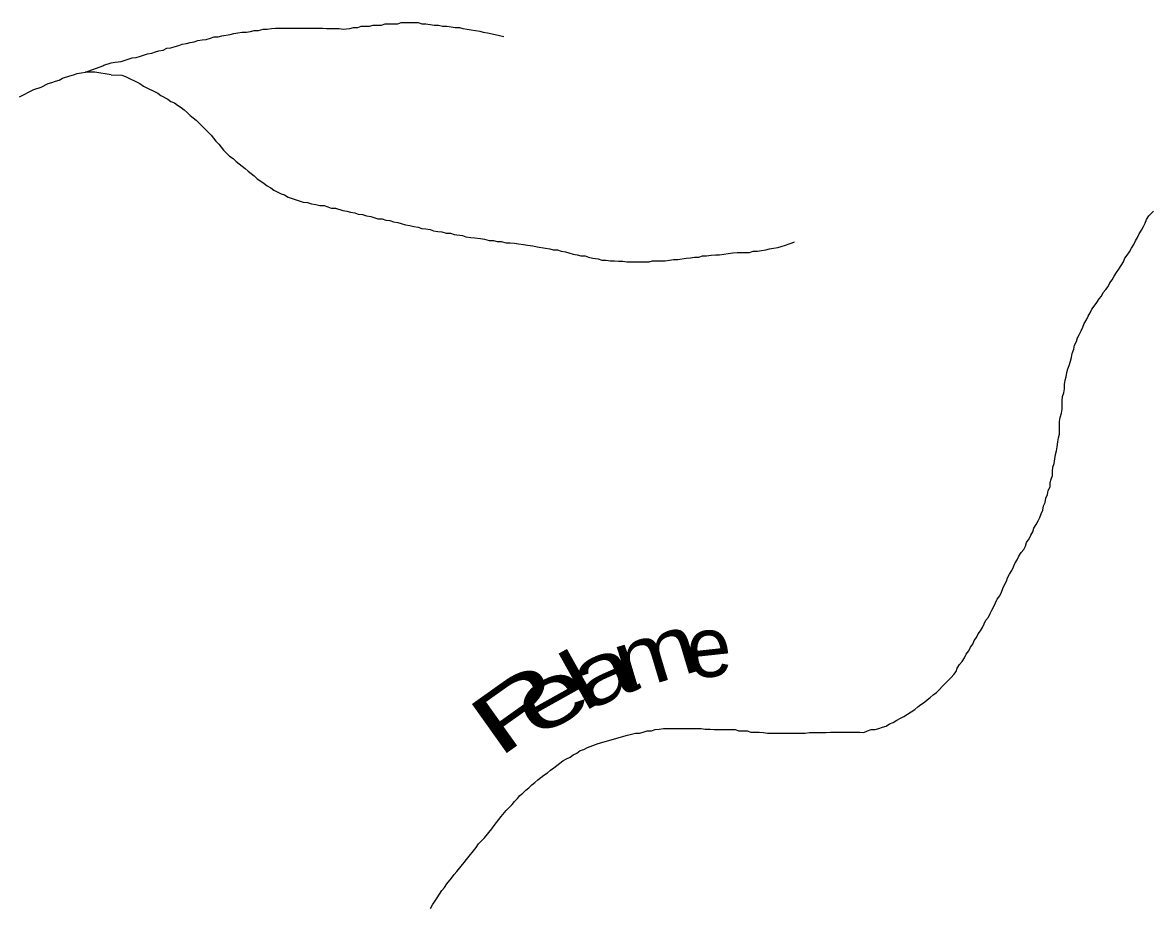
# Model space of a CAD drawing. Extents: x 652.3 to 678, y 7316.9 to 7344.9.
# Drawn here: x 662.771 to 664.275, y 7321.355 to 7322.532 of the extents above; entities that cross this region are included whole.
import ezdxf
from ezdxf.enums import TextEntityAlignment as Align

# ---------------------------------------------------------------- set-up
doc = ezdxf.new("R2010")
doc.units = 0
doc.header["$LTSCALE"] = 0.032
doc.layers.add('61', color=7, linetype='Continuous')
doc.layers.add('7', color=7, linetype='Continuous', lineweight=25)

msp = doc.modelspace()

# ---------------------------------------------------------------- linework, layer by layer
at = {"layer": '7'}
for points in [[(662.878, 7322.4749), (662.8796, 7322.4757), (662.8891, 7322.4789), (662.8947, 7322.4797), (662.9027, 7322.4805), (662.917, 7322.4852), (662.9225, 7322.486), (662.9281, 7322.4876), (662.9377, 7322.4908), (662.9432, 7322.4916), (662.948, 7322.4932), (662.9528, 7322.4948), (662.9584, 7322.4956), (662.9631, 7322.498), (662.9687, 7322.4988), (662.9743, 7322.5003), (662.979, 7322.5019), (662.9838, 7322.5035), (662.9894, 7322.5043), (662.9942, 7322.5059), (662.9997, 7322.5067), (663.0045, 7322.5083), (663.0101, 7322.5091), (663.0156, 7322.5099), (663.0212, 7322.5115), (663.026, 7322.5131), (663.0316, 7322.5131), (663.0363, 7322.5147), (663.0475, 7322.5163), (663.0522, 7322.5179), (663.0578, 7322.5186), (663.0634, 7322.5194), (663.069, 7322.5194), (663.0745, 7322.5202), (663.0793, 7322.5218), (663.0849, 7322.5218), (663.0912, 7322.5234), (663.0968, 7322.5234), (663.1024, 7322.5242), (663.1079, 7322.525), (663.17, 7322.525), (663.1756, 7322.5242), (663.1923, 7322.5242), (663.1979, 7322.5234), (663.2066, 7322.5242), (663.2114, 7322.5258), (663.217, 7322.5258), (663.2217, 7322.5274), (663.2329, 7322.5274), (663.2376, 7322.529), (663.2488, 7322.529), (663.2536, 7322.5306), (663.2703, 7322.5306), (663.275, 7322.5322), (663.2973, 7322.5322), (663.3021, 7322.5306), (663.3077, 7322.5306), (663.3132, 7322.5298), (663.3188, 7322.529), (663.3244, 7322.529), (663.3299, 7322.5274), (663.3355, 7322.5274), (663.3411, 7322.5266), (663.3467, 7322.5258), (663.3522, 7322.5258), (663.357, 7322.5242), (663.3626, 7322.5234), (663.3681, 7322.5226), (663.3793, 7322.521), (663.384, 7322.5194), (663.3896, 7322.5186), (663.4, 7322.5163), (663.4112, 7322.5137)], [(662.8549, 7322.4661), (662.8549, 7322.4661), (662.878, 7322.4749)], [(662.7674, 7322.4335), (662.7865, 7322.4431), (662.796, 7322.4462), (662.8056, 7322.451), (662.8104, 7322.4526), (662.8151, 7322.4542), (662.8199, 7322.4558), (662.8247, 7322.4582), (662.8342, 7322.4614), (662.839, 7322.4629), (662.8438, 7322.4645), (662.8493, 7322.4653), (662.8549, 7322.4661)], [(662.8891, 7322.4629), (662.8676, 7322.4661), (662.8549, 7322.4661)], [(662.8891, 7322.4629), (662.9035, 7322.4622), (662.9082, 7322.4606), (662.9273, 7322.451), (662.9321, 7322.4478), (662.9512, 7322.4383), (662.9552, 7322.4351), (662.9647, 7322.4303), (662.9687, 7322.4271), (662.9735, 7322.4256), (662.9775, 7322.4224), (662.9822, 7322.4192), (662.9862, 7322.416), (662.9902, 7322.4128), (662.9942, 7322.4088), (662.9981, 7322.4057), (663.0021, 7322.4025), (663.018, 7322.3866), (663.022, 7322.3826), (663.0284, 7322.3746), (663.0324, 7322.3706), (663.0387, 7322.3627), (663.0467, 7322.3547), (663.0514, 7322.3516), (663.0554, 7322.3476), (663.0594, 7322.3444), (663.0634, 7322.3412), (663.0674, 7322.338), (663.0713, 7322.3348), (663.0753, 7322.3317), (663.0793, 7322.3285), (663.0833, 7322.3245), (663.0881, 7322.3213), (663.0928, 7322.3181), (663.0968, 7322.315), (663.1016, 7322.3126), (663.1056, 7322.3094), (663.1151, 7322.3046), (663.1199, 7322.303), (663.1247, 7322.2998), (663.139, 7322.2951), (663.1445, 7322.2935), (663.1501, 7322.2927), (663.1557, 7322.2911), (663.1613, 7322.2903), (663.1668, 7322.2887), (663.1724, 7322.2887), (663.1772, 7322.2871), (663.1819, 7322.2855), (663.1875, 7322.2855), (663.1971, 7322.2823), (663.2026, 7322.2815), (663.2074, 7322.2799), (663.213, 7322.2791), (663.2177, 7322.2776), (663.2233, 7322.2768), (663.2289, 7322.2752), (663.2345, 7322.2744), (663.244, 7322.2712), (663.2496, 7322.2712), (663.2544, 7322.2696), (663.2599, 7322.2688), (663.2647, 7322.2672), (663.2703, 7322.2664), (663.275, 7322.2648), (663.2806, 7322.2632), (663.2862, 7322.2624), (663.2917, 7322.2608), (663.2973, 7322.26), (663.3021, 7322.2585), (663.3077, 7322.2577), (663.3132, 7322.2569), (663.318, 7322.2553), (663.3236, 7322.2545), (663.3291, 7322.2537), (663.3347, 7322.2521), (663.3403, 7322.2521), (663.3451, 7322.2505), (663.3562, 7322.2489), (663.361, 7322.2473), (663.3673, 7322.2465), (663.3729, 7322.2457), (663.3801, 7322.2449), (663.3856, 7322.2441), (663.392, 7322.2425), (663.3976, 7322.2425), (663.4023, 7322.241), (663.4079, 7322.241), (663.4143, 7322.2394), (663.4199, 7322.2394), (663.4254, 7322.2386), (663.431, 7322.2378), (663.4374, 7322.237), (663.4429, 7322.2362), (663.4501, 7322.2354), (663.4557, 7322.2338), (663.4668, 7322.2322), (663.4724, 7322.2314), (663.4771, 7322.2298), (663.4827, 7322.2298), (663.4875, 7322.2282)], [(664.1161, 7321.8598), (664.1193, 7321.8646), (664.1217, 7321.8694), (664.124, 7321.8741), (664.1256, 7321.8789), (664.128, 7321.8837), (664.1288, 7321.8893), (664.1312, 7321.894), (664.132, 7321.8996), (664.1344, 7321.9044), (664.1352, 7321.9099), (664.1376, 7321.9147), (664.1376, 7321.9203), (664.1392, 7321.9251), (664.1407, 7321.9298), (664.1407, 7321.9354), (664.1415, 7321.941), (664.1431, 7321.9458), (664.1439, 7321.9521), (664.1447, 7321.9577), (664.1463, 7321.9625), (664.1471, 7321.968), (664.1479, 7321.9744), (664.1487, 7321.98), (664.1503, 7321.9847), (664.1503, 7321.9903), (664.1503, 7321.9959), (664.1503, 7322.0014), (664.1511, 7322.007), (664.1527, 7322.0126), (664.1535, 7322.0182), (664.1535, 7322.0237), (664.1535, 7322.0293), (664.1543, 7322.0349), (664.1559, 7322.0396), (664.1567, 7322.0452), (664.1567, 7322.0508), (664.1575, 7322.0564), (664.159, 7322.0611), (664.1598, 7322.0667), (664.1614, 7322.0715), (664.163, 7322.0762), (664.1646, 7322.0818), (664.1662, 7322.0866), (664.167, 7322.0922), (664.1694, 7322.0977), (664.1702, 7322.1033), (664.1726, 7322.1081), (664.1742, 7322.1128), (664.1766, 7322.1176), (664.1789, 7322.1224), (664.1813, 7322.1272), (664.1829, 7322.1319), (664.1861, 7322.1367), (664.1885, 7322.1415), (664.1909, 7322.1463), (664.1933, 7322.151), (664.1964, 7322.155), (664.1996, 7322.1598), (664.2028, 7322.1646), (664.206, 7322.1685), (664.2084, 7322.1733), (664.2116, 7322.1773), (664.2147, 7322.1813), (664.2171, 7322.186), (664.2203, 7322.19), (664.2227, 7322.1948), (664.2259, 7322.1996), (664.2291, 7322.2044), (664.2323, 7322.2091), (664.2354, 7322.2139), (664.237, 7322.2187), (664.2402, 7322.2227), (664.2434, 7322.2274), (664.2458, 7322.2322), (664.249, 7322.237), (664.2513, 7322.2417), (664.2537, 7322.2465), (664.2561, 7322.2513), (664.2593, 7322.2561), (664.2617, 7322.2608), (664.2641, 7322.2656), (664.2657, 7322.2704), (664.2689, 7322.2752), (664.2744, 7322.2807), (664.275, 7322.2813)], [(663.4875, 7322.2282), (663.4931, 7322.2274), (663.4978, 7322.2258), (663.5034, 7322.2242), (663.509, 7322.2234), (663.5137, 7322.2219), (663.5193, 7322.2219), (663.5241, 7322.2203), (663.5297, 7322.2187), (663.5368, 7322.2179), (663.5416, 7322.2163), (663.5472, 7322.2163), (663.5527, 7322.2155), (663.5583, 7322.2155), (663.5639, 7322.2147), (663.5694, 7322.2147), (663.575, 7322.2139), (663.6045, 7322.2139), (663.6092, 7322.2155), (663.6259, 7322.2155), (663.6315, 7322.2163), (663.6371, 7322.2171), (663.6426, 7322.2171), (663.6538, 7322.2187), (663.6594, 7322.2195), (663.6649, 7322.2203), (663.6705, 7322.2203), (663.6753, 7322.2219), (663.6808, 7322.2219), (663.6872, 7322.2227), (663.6928, 7322.2234), (663.6983, 7322.2234), (663.7095, 7322.225), (663.7158, 7322.2258), (663.7214, 7322.2266), (663.7381, 7322.2266), (663.7429, 7322.2282), (663.7485, 7322.2282), (663.754, 7322.229), (663.7596, 7322.2298), (663.7644, 7322.2314), (663.77, 7322.2322), (663.7755, 7322.233), (663.7803, 7322.2346), (663.7859, 7322.2362), (663.7906, 7322.2378), (663.7946, 7322.2394), (663.7976, 7322.2405), (663.7979, 7322.2407)], [(663.719, 7321.5917), (663.7238, 7321.5901), (663.7294, 7321.5901), (663.7349, 7321.5901), (663.7397, 7321.5885), (663.7453, 7321.5885), (663.7509, 7321.5885), (663.7564, 7321.5877), (663.762, 7321.5869), (663.7676, 7321.5869), (663.7731, 7321.5869), (663.7787, 7321.5869), (663.7843, 7321.5869), (663.7898, 7321.5869), (663.7954, 7321.5869), (663.801, 7321.5869), (663.8066, 7321.5869), (663.8121, 7321.5869), (663.8177, 7321.5877), (663.8233, 7321.5877), (663.8288, 7321.5877), (663.8344, 7321.5877), (663.84, 7321.5877), (663.8455, 7321.5885), (663.8511, 7321.5885), (663.8567, 7321.5885), (663.8623, 7321.5885), (663.8678, 7321.5885), (663.8734, 7321.5885), (663.879, 7321.5885), (663.8845, 7321.5885), (663.8901, 7321.5877), (663.8949, 7321.5901), (663.8997, 7321.5917), (663.9052, 7321.5917), (663.91, 7321.5933), (663.9148, 7321.5949), (663.9195, 7321.5964), (663.9243, 7321.5996), (663.9291, 7321.6012), (663.9339, 7321.6044), (663.9386, 7321.6068), (663.9434, 7321.6092), (663.9482, 7321.6124), (663.953, 7321.6155), (663.9577, 7321.6187), (663.9617, 7321.6219), (663.9657, 7321.6251), (663.9705, 7321.6283), (663.9744, 7321.6315), (663.9784, 7321.6346), (663.9824, 7321.6378), (663.9864, 7321.641), (663.9904, 7321.645), (663.9943, 7321.649), (663.9983, 7321.6529), (664.0023, 7321.6569), (664.0063, 7321.6609), (664.0095, 7321.6649), (664.0126, 7321.6689), (664.0142, 7321.6736), (664.0174, 7321.6784), (664.0206, 7321.6824), (664.0238, 7321.6872), (664.0262, 7321.6919), (664.0294, 7321.6967), (664.0317, 7321.7015), (664.0349, 7321.7055), (664.0365, 7321.7102), (664.0397, 7321.7142), (664.0421, 7321.719), (664.0453, 7321.723), (664.0477, 7321.7277), (664.05, 7321.7325), (664.0524, 7321.7373), (664.0556, 7321.7413), (664.058, 7321.746), (664.0604, 7321.7508), (664.0628, 7321.7556), (664.0652, 7321.7604), (664.0675, 7321.7651), (664.0707, 7321.7699), (664.0731, 7321.7747), (664.0747, 7321.7795), (664.0771, 7321.7842), (664.0795, 7321.789), (664.0811, 7321.7938), (664.0835, 7321.7985), (664.0866, 7321.8033), (664.089, 7321.8081), (664.0906, 7321.8129), (664.0938, 7321.8176), (664.0962, 7321.8224), (664.0994, 7321.8272), (664.1026, 7321.8312), (664.1049, 7321.8359), (664.1065, 7321.8407), (664.1097, 7321.8455), (664.1121, 7321.8503), (664.1145, 7321.855), (664.1161, 7321.8598)], [(663.314, 7321.3538), (663.3164, 7321.3585), (663.3228, 7321.3681), (663.326, 7321.3729), (663.3291, 7321.3776), (663.3323, 7321.3816), (663.3355, 7321.3864), (663.3419, 7321.3943), (663.3451, 7321.3991), (663.349, 7321.4031), (663.3586, 7321.415), (663.3618, 7321.419), (663.3745, 7321.4349), (663.3777, 7321.4397), (663.3856, 7321.4477), (663.3952, 7321.4596), (663.3984, 7321.4644), (663.4047, 7321.4723), (663.4079, 7321.4763), (663.4143, 7321.4843), (663.4222, 7321.4922), (663.4254, 7321.4962), (663.4294, 7321.5002), (663.4326, 7321.5041), (663.4366, 7321.5073), (663.4405, 7321.5113), (663.4445, 7321.5145), (663.4485, 7321.5185), (663.4525, 7321.5216), (663.4565, 7321.5248), (663.4604, 7321.528), (663.4644, 7321.5312), (663.4692, 7321.5344), (663.4732, 7321.5376), (663.4779, 7321.5407), (663.4819, 7321.5439), (663.4859, 7321.5471), (663.4899, 7321.5503), (663.4946, 7321.5527), (663.4994, 7321.5551), (663.5034, 7321.5583), (663.5082, 7321.5606), (663.5129, 7321.5638), (663.5177, 7321.5654), (663.5225, 7321.5678), (663.5368, 7321.5734), (663.5758, 7321.5845), (663.5862, 7321.5869), (663.5917, 7321.5869), (663.5965, 7321.5885), (663.6021, 7321.5901), (663.6076, 7321.5901), (663.6124, 7321.5917), (663.618, 7321.5925), (663.6235, 7321.5933), (663.6291, 7321.5933), (663.6347, 7321.5933), (663.6403, 7321.5933), (663.6458, 7321.5933), (663.6514, 7321.5933), (663.657, 7321.5933), (663.6625, 7321.5933), (663.6681, 7321.5933), (663.6737, 7321.5933), (663.6792, 7321.5925), (663.6856, 7321.5925), (663.6912, 7321.5917), (663.6968, 7321.5917), (663.7023, 7321.5917), (663.7079, 7321.5917), (663.7135, 7321.5917), (663.719, 7321.5917)]]:
    msp.add_lwpolyline(points, dxfattribs=at)

# ---------------------------------------------------------------- texts
at = {"layer": '61'}
for s, rotation, width, p in [('m', 16.711, 1.25, (663.6237, 7321.6561)), ('l', 29.186, 1.35, (663.5308, 7321.6224)), ('a', 22.949, 1.35, (663.5575, 7321.6317)), ('P', 35.424, 1.7, (663.4525, 7321.5871)), ('e', 29.186, 1.6, (663.4922, 7321.6021))]:
    msp.add_text(s, height=0.08, rotation=rotation, dxfattribs=dict(at, width=width)).set_placement(p, align=Align.CENTER)
msp.add_text('e', height=0.08, rotation=6.161, dxfattribs=at).set_placement((663.6879, 7321.6621), align=Align.CENTER)

doc.saveas('drawing.dxf')
